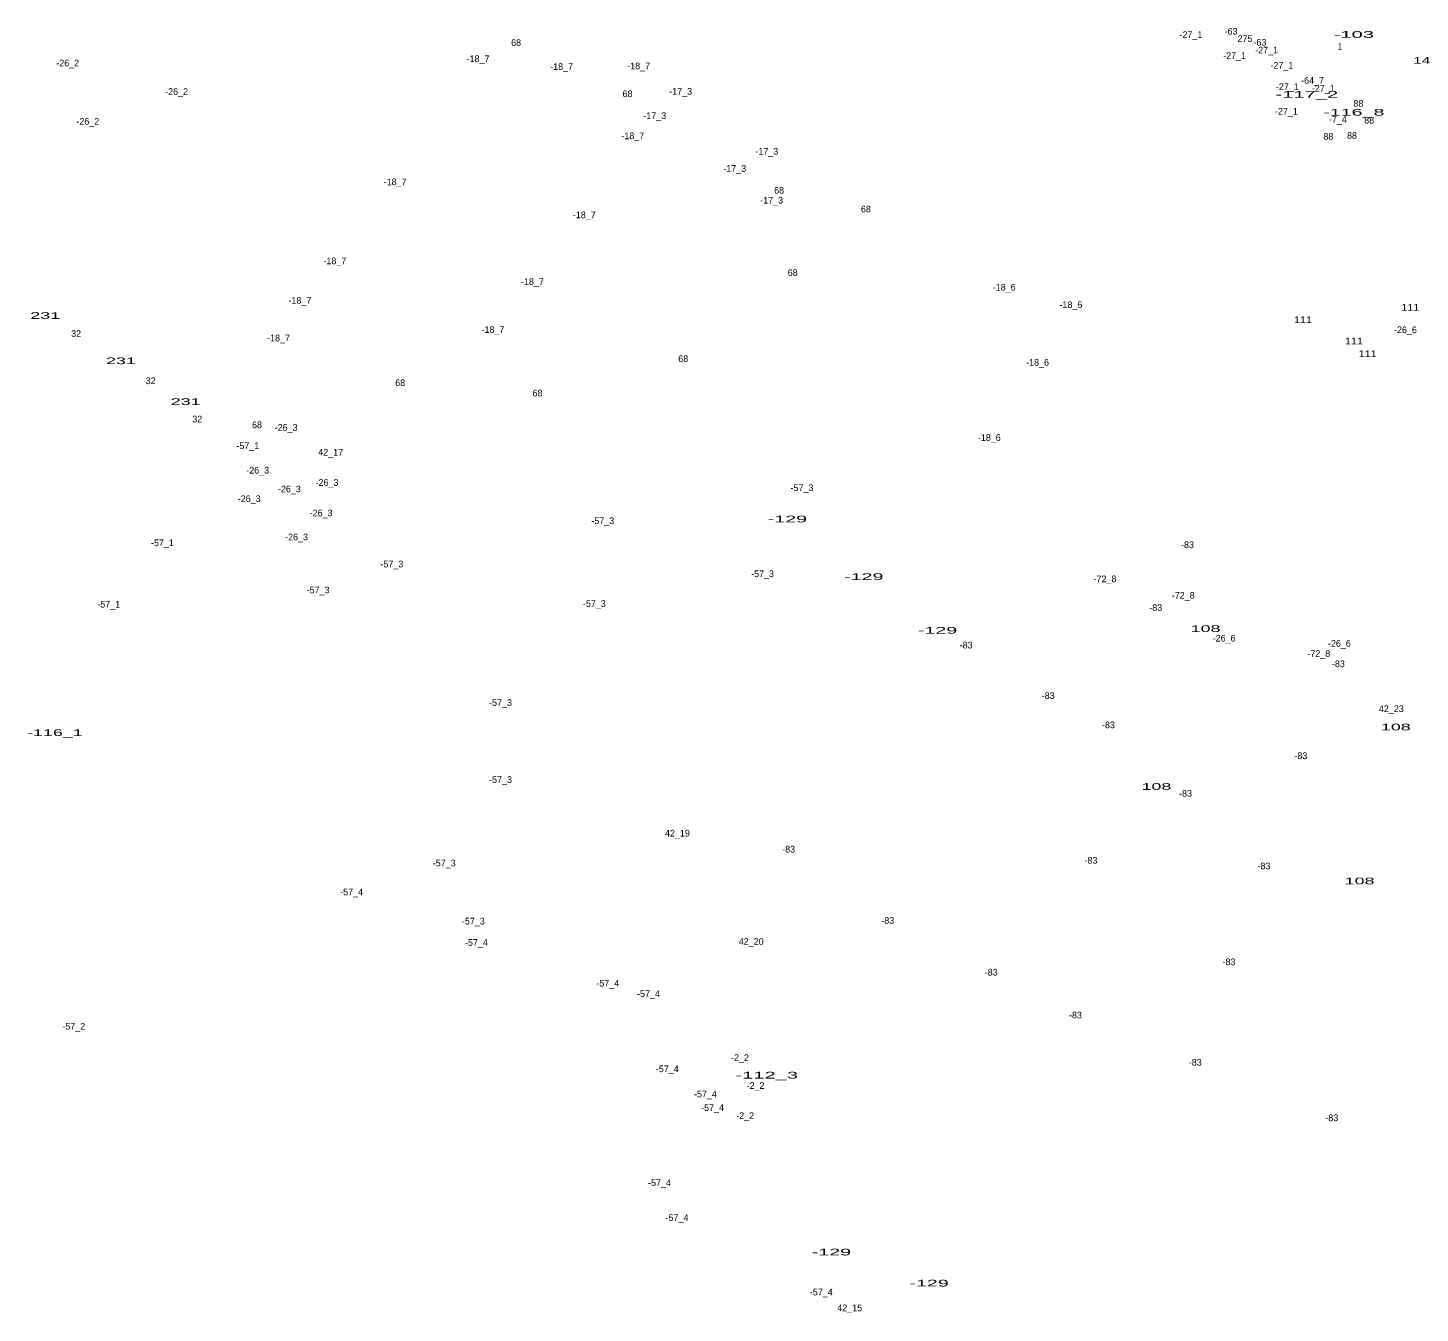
# Model space of a CAD drawing. Extents: x -656096 to -652763, y -1002270 to -998958.
# Drawn here: x -654897 to -654064, y -1002237 to -1001467 of the extents above; entities that cross this region are included whole.
import ezdxf
from ezdxf.enums import TextEntityAlignment as Align

# ---------------------------------------------------------------- set-up
doc = ezdxf.new("R2010")
doc.units = 0
doc.header["$LTSCALE"] = 1.6
doc.layers.add('24', color=7, linetype='Continuous')

msp = doc.modelspace()

# ---------------------------------------------------------------- texts
at = {"layer": '24'}
for s, p in [('-27_1', (-654200.782, -1001473.19)), ('-63', (-654176.71, -1001471.15)), ('68', (-654604.673, -1001477.92)), ('275', (-654168.353, -1001475.53)), ('-63', (-654159.47, -1001477.74)), ('-27_1', (-654155.412, -1001482.43)), ('-26_2', (-654873.058, -1001490.17)), ('-18_7', (-654627.472, -1001487.62)), ('-27_1', (-654174.612, -1001485.73)), ('-18_7', (-654577.452, -1001492.24)), ('-18_7', (-654531.312, -1001491.89)), ('-27_1', (-654146.302, -1001491.55)), ('-26_2', (-654807.918, -1001507.24)), ('-17_3', (-654506.182, -1001507.13)), ('-27_1', (-654143.042, -1001504.31)), ('-64_7', (-654127.948, -1001500.57)), ('-27_1', (-654121.522, -1001505.28)), ('68', (-654537.973, -1001508.56)), ('88', (-654100.467, -1001514.31)), ('-17_3', (-654521.692, -1001521.68)), ('-27_1', (-654143.592, -1001519.08)), ('-7_4', (-654112.803, -1001523.88)), ('88', (-654094.067, -1001524.39)), ('-26_2', (-654861.038, -1001525.08)), ('-18_7', (-654534.802, -1001533.75)), ('88', (-654118.497, -1001534.09)), ('88', (-654104.337, -1001533.51)), ('-17_3', (-654454.612, -1001543.01)), ('-17_3', (-654473.802, -1001553.29)), ('-18_7', (-654677.102, -1001561.32)), ('-17_3', (-654451.702, -1001572.29)), ('68', (-654447.243, -1001566.35)), ('-18_7', (-654563.882, -1001581.07)), ('68', (-654395.293, -1001577.6)), ('-18_7', (-654713.162, -1001608.61)), ('68', (-654439.103, -1001615.62)), ('-18_7', (-654594.902, -1001621.02)), ('-18_6', (-654312.522, -1001624.38)), ('-18_7', (-654734.102, -1001632.27)), ('-18_6', (-654272.582, -1001634.85)), ('32', (-654868.037, -1001652.08)), ('-18_7', (-654746.892, -1001654.76)), ('-18_7', (-654618.552, -1001649.72)), ('-26_6', (-654072.323, -1001649.88)), ('68', (-654504.633, -1001667.2)), ('-18_6', (-654292.552, -1001669.37)), ('32', (-654823.447, -1001680.39)), ('68', (-654674.073, -1001681.55)), ('68', (-654591.873, -1001687.76)), ('32', (-654795.537, -1001703.28)), ('68', (-654759.763, -1001706.77)), ('-26_3', (-654742.328, -1001708.33)), ('-18_6', (-654321.432, -1001714.36)), ('-57_1', (-654765.272, -1001719.27)), ('42_17', (-654715.638, -1001723.17)), ('-26_3', (-654759.388, -1001733.93)), ('-26_3', (-654740.388, -1001745.18)), ('-26_3', (-654717.898, -1001741.3)), ('-57_3', (-654433.538, -1001744.42)), ('-26_3', (-654764.428, -1001751)), ('-26_3', (-654721.388, -1001759.53)), ('-57_3', (-654552.818, -1001764.18)), ('-26_3', (-654736.118, -1001773.88)), ('-57_1', (-654816.392, -1001777.38)), ('-83', (-654202.805, -1001778.58)), ('-57_3', (-654679.068, -1001790.13)), ('-57_3', (-654457.168, -1001795.94)), ('-72_8', (-654252.218, -1001798.99)), ('-57_3', (-654723.218, -1001805.63)), ('-57_1', (-654848.532, -1001814.18)), ('-57_3', (-654557.858, -1001813.76)), ('-72_8', (-654205.358, -1001808.87)), ('-83', (-654221.805, -1001816.2)), ('-83', (-654335.295, -1001838.64)), ('-26_6', (-654180.893, -1001834.51)), ('-26_6', (-654111.873, -1001837.62)), ('-72_8', (-654124.228, -1001843.74)), ('-83', (-654112.465, -1001849.84)), ('-57_3', (-654614.008, -1001873.04)), ('-83', (-654286.165, -1001868.85)), ('42_23', (-654080.79, -1001876.72)), ('-83', (-654250.105, -1001886.41)), ('-83', (-654134.945, -1001904.92)), ('-57_3', (-654614.008, -1001919.14)), ('-83', (-654203.965, -1001927.42)), ('42_19', (-654508.118, -1001951.24)), ('-83', (-654441.535, -1001960.82)), ('-57_3', (-654647.698, -1001969.12)), ('-83', (-654260.575, -1001967.48)), ('-83', (-654157.045, -1001970.86)), ('-57_4', (-654703.172, -1001986.45)), ('-57_3', (-654630.278, -1002003.89)), ('-83', (-654382.205, -1002003.49)), ('42_20', (-654463.974, -1002016.08)), ('-57_4', (-654628.432, -1002016.67)), ('-83', (-654177.985, -1002028.27)), ('-57_4', (-654549.812, -1002041.08)), ('-83', (-654320.285, -1002034.47)), ('-57_4', (-654525.422, -1002047.37)), ('-83', (-654269.885, -1002060.13)), ('-57_2', (-654869.448, -1002066.89)), ('-2_2', (-654470.683, -1002085.63)), ('-83', (-654198.145, -1002088.39)), ('-57_4', (-654514.192, -1002092.31)), ('-57_4', (-654491.342, -1002107.42)), ('-2_2', (-654461.373, -1002102.31)), ('-57_4', (-654487.082, -1002115.55)), ('-2_2', (-654467.583, -1002120.35)), ('-83', (-654116.415, -1002121.64)), ('-57_4', (-654518.832, -1002160.49)), ('-57_4', (-654508.382, -1002181.41)), ('-57_4', (-654422.022, -1002225.96)), ('42_15', (-654404.983, -1002235.44))]:
    msp.add_text(s, height=4, dxfattribs=at).set_placement(p, align=Align.CENTER)
for s, width, p in [('-103', 2.25, (-654103.237, -1001473.06)), ('1', 0.65, (-654111.587, -1001480.25)), ('14', 1.7, (-654062.633, -1001488.63)), ('-117_2', 2.25, (-654131.333, -1001508.94)), ('-116_8', 2.2, (-654103.253, -1001519.63)), ('111', 1.2, (-654069.46, -1001636.38)), ('231', 2, (-654886.527, -1001641.32)), ('111', 1.2, (-654133.65, -1001643.85)), ('111', 1.2, (-654103.15, -1001656.53)), ('111', 1.2, (-654094.92, -1001664.18)), ('231', 2, (-654841.217, -1001668.44)), ('231', 2, (-654802.487, -1001692.85)), ('-129', 2.2, (-654442.255, -1001763.15)), ('-129', 2.2, (-654396.565, -1001797.63)), ('-129', 2.2, (-654352.415, -1001829.79)), ('108', 2, (-654191.964, -1001828.76)), ('-116_1', 2, (-654880.759, -1001891.03)), ('108', 2, (-654078.104, -1001887.65)), ('108', 2, (-654221.394, -1001923.29)), ('108', 2, (-654099.794, -1001979.85)), ('-112_3', 2.25, (-654454.657, -1002096.11)), ('-129', 2.2, (-654415.965, -1002202.04)), ('-129', 2.2, (-654357.485, -1002220.63))]:
    msp.add_text(s, height=4, dxfattribs=dict(at, width=width)).set_placement(p, align=Align.CENTER)

doc.saveas('drawing.dxf')
